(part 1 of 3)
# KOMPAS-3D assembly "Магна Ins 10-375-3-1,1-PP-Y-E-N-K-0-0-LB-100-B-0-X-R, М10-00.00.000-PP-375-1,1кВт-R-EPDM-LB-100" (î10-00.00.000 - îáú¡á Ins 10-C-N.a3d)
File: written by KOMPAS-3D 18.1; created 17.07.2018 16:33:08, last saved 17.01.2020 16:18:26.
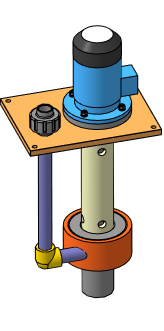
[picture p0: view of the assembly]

Document properties: Автор: Милов; Полное имя файла: C:\Users\User\Desktop\Магна 10 для Караби\М10-00.00.000 - Магна Ins 10-C-N.a3d

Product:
- Part/product: Магна Ins 10-375-3-1,1-PP-Y-E-N-K-0-0-LB-100-B-0-X-R  | designation М10-00.00.000-PP-375-1,1кВт-R-EPDM-LB-100
    Материал: Полипропилен  ГОСТ 26996-86 (density 900 kg/m3)
    Масса: 14.8749
  - Component [detail]: Всасывающая трубка 75  | designation L=100  | pos. 1375
      Материал: Полипропилен  ГОСТ 26996-86 (density 900 kg/m3)
      Масса: 0.190378
      Раздел спецификации: Детали
      Форматы листов документа: 3xA3
      Примечание: @100~)3xA3
      source file: D:\Magna\Магна Ins\Магна ins 11\Магна N\3Д\Магна INS 11\Всасывающая трубка 75.m3d, D:\Magna\Магна Ins\Магна ins 11\Магна N\3Д\Магна INS 11\Чертежи\М11-00.00.004-01 - Крышка.cdw
  - Component [detail]: Заглушка @2~25 FV PPR ф. "FV-Plast"  | qty 4  | pos. 12  | Материал: Полипропилен  ГОСТ 26996-86 (density 900 kg/m3); Масса: 0.0161976; Раздел спецификации: Прочие изделия
  - Component [standard]: Болт М10x1,25-6gx60 (S16) ГОСТ 7798-70  | qty 4  | pos. 8  | Масса: 0.0467; Раздел спецификации: Стандартные изделия; Рассекать на разрезах: no; additional columns: Сталь 12Х18Н10Т ГОСТ 5632-72
  - Component [standard]: Гайка М10x1,25-6H(S16) ГОСТ 5915-70  | qty 4  | pos. 9  | Масса: 0.01022; Раздел спецификации: Стандартные изделия; additional columns: М8-6H.21.12Х18Н10Т; Сталь 12Х18Н10Т ГОСТ 5632-72
  - Component [standard]: Шайба 10 ГОСТ 6402-70  | qty 4  | pos. 10  | Масса: 0.00201; Раздел спецификации: Стандартные изделия; Примечание: Нерж.; additional columns: 8; Без указания материала
  - Component [standard]: Шайба C.10.21 ГОСТ 11371-78  | qty 4  | pos. 11  | Материал: Сталь 12Х18Н10Т ГОСТ 5632-72 (density 1000 kg/m3); Масса: 0.003438; Раздел спецификации: Стандартные изделия; Рассекать на разрезах: no; additional columns: Сталь 12Х18Н10Т ГОСТ 5632-72
  - Component [standard]: Шайба C.10.21 ГОСТ 11371-78  | qty 4  | pos. 11  | Материал: Сталь 12Х18Н10Т ГОСТ 5632-72 (density 1000 kg/m3); Масса: 0.003438; Раздел спецификации: Стандартные изделия; additional columns: C.8.21; Сталь 12Х18Н10Т ГОСТ 5632-72
  - Component [detail]: Втулка ответная  | designation М10А-00.00.003-01  | pos. 6  | Масса: 0.031838; Раздел спецификации: Детали; Форматы листов документа: A4; Примечание: Заим.; source file: D:\AquaProf\АкваProf 190\3Д модель\..\..\..\Magna\Магна Ins\Магна ins 10\М10-00.00.000\3Д\М10А-00.00.003-01 - Втулка ответная.cdw, D:\AquaProf\АкваProf 190\3Д модель\М10А-00.00.003 - Втулка ответная.m3d
  - Component [detail]: Защитная втулка  | designation М10-00.00.003  | pos. 5  | Масса: 0.0193569; Раздел спецификации: Детали; Форматы листов документа: A4; source file: D:\Magna\Магна Ins\Магна ins 10\М10-00.00.000\3Д\М10-00.00.003 - Защитная втулка.cdw, М10-00.00.003 - Защитная втулка.m3d
  - Component [detail]: Импеллер Магна10  | designation М10-00.00.001  | pos. 3  | Масса: 0.169927; Раздел спецификации: Детали; Форматы листов документа: A3; source file: М10-00.00.001 - Импеллер Магна10.cdw, М10-00.00.001 - Импеллер Магна10.m3d
  - Component [detail]: Крышка  | designation М10-00.00.002-01  | pos. 4
      Материал: Полипропилен  ГОСТ 26996-86 (density 900 kg/m3)
      Масса: 0.284697
      Раздел спецификации: Детали
      Форматы листов документа: 4xA4
      Примечание: @100~)4xA4
      source file: М10-00.00.002 - Крышка.cdw, М10-00.00.002 - Крышка.m3d
  - Component [detail]: Электродвигатель / АИР 71B2 IM 3081 IP55 ф."Элком"  | pos. 14  | Масса: 8.3; Раздел спецификации: Прочие изделия; Примечание: См. заказ
  - Component [assembly]: Корпус полипропилен 375 1,1кВт  / с резьбовым переходником  | designation М10-00.20.000-PP-375-1,1кВт-R  | pos. 2  | Материал: Полипропилен  ГОСТ 26996-86 (density 900 kg/m3); Масса: 4.74348; Раздел спецификации: Сборочные единицы; Форматы листов документа: 3xA3; Примечание: @100~)3xA3@101~)3xA3
  - Component [standard]: Кольцо 125-130-25-1-0 ГОСТ 9833-73  | pos. 16  | Материал: Смесь резиновая ИРП-1068 ТУ 38-1051082-86 (density 1280 kg/m3); Масса: 0.00019; Раздел спецификации: Стандартные изделия; Рассекать на разрезах: no; additional columns: 125-130-25-1-0
  - Component [standard]: Кольцо 058-064-36-1-0 ГОСТ 9833-73  | pos. 15  | Материал: Смесь резиновая ИРП-1068 ТУ 38-1051082-86 (density 1280 kg/m3); Масса: 0.00194; Раздел спецификации: Стандартные изделия; Рассекать на разрезах: no; additional columns: 058-064-36-1-0
- Part/product: Магна Ins 10-375-3-0,55-PP-Y-V-N-K-0-0-L-0-B-0-X-R  | designation М10-00.00.000-PP-375-0,55кВт-R-Viton
    Материал: Полипропилен  ГОСТ 26996-86 (density 900 kg/m3)
    Масса: 11.3082
  - Component [detail]: Втулка ответная  | designation М10А-00.00.003-01  | pos. 6  | Масса: 0.031838; Раздел спецификации: Детали; Форматы листов документа: A4; Примечание: Заим.; source file: D:\AquaProf\АкваProf 190\3Д модель\..\..\..\Magna\Магна Ins\Магна ins 10\М10-00.00.000\3Д\М10А-00.00.003-01 - Втулка ответная.cdw, D:\AquaProf\АкваProf 190\3Д модель\М10А-00.00.003 - Втулка ответная.m3d
  - Component [detail]: Защитная втулка  | designation М10-00.00.003  | pos. 5  | Масса: 0.0193569; Раздел спецификации: Детали; Форматы листов документа: A4; source file: D:\Magna\Магна Ins\Магна ins 10\М10-00.00.000\3Д\М10-00.00.003 - Защитная втулка.cdw, М10-00.00.003 - Защитная втулка.m3d
  - Component [detail]: Импеллер Магна10  | designation М10-00.00.001  | pos. 3  | Масса: 0.169927; Раздел спецификации: Детали; Форматы листов документа: A3; source file: М10-00.00.001 - Импеллер Магна10.cdw, М10-00.00.001 - Импеллер Магна10.m3d
  - Component [detail]: Крышка  | designation М10-00.00.002  | pos. 4
      Материал: Полипропилен  ГОСТ 26996-86 (density 900 kg/m3)
      Масса: 0.324102
      Раздел спецификации: Детали
      Форматы листов документа: 4xA4
      Примечание: @100~)4xA4
      source file: М10-00.00.002 - Крышка.cdw, М10-00.00.002 - Крышка.m3d
  - Component [assembly]: Вал  | designation М10-00.15.000-0,55кВт-375  | pos. 1
      Материал: Полипропилен  ГОСТ 26996-86 (density 900 kg/m3)
      Масса: 0.519317
      Раздел спецификации: Сборочные единицы
      Форматы листов документа: 2xA3
      Примечание: @100~)2xA3
      source file: М10-00.15.000 - Вал.a3d
  - Component [assembly]: Корпус полипропилен 375 0,55 кВт  / с резьбовым переходником  | designation М10-00.20.000-PP-375-0,55кВт-R  | pos. 2
      Материал: Полипропилен  ГОСТ 26996-86 (density 900 kg/m3)
      Масса: 4.99986
      Раздел спецификации: Сборочные единицы
      Форматы листов документа: 3xA3
      Примечание: @100~)3xA3@101~)3xA3
      source file: М10-00.20.000 - Корпус.a3d
  - Component [detail]: Кольцо уплотнительное плоское 10-18-25  | designation Viton  | pos. 13  | Масса: 0.000562973; Раздел спецификации: Прочие изделия
- Part/product: Магна Ins 10-375-3-0,55-PP-Y-V-N-K-0-0-L-0-B-0-X-M  | designation М10-00.00.000-PP-375-0,55кВт-M-Viton
    Материал: Полипропилен  ГОСТ 26996-86 (density 900 kg/m3)
    Масса: 12.2247
  - Component [detail]: Втулка ответная  | designation М10А-00.00.003-01  | pos. 6  | Масса: 0.031838; Раздел спецификации: Детали; Форматы листов документа: A4; Примечание: Заим.; source file: D:\AquaProf\АкваProf 190\3Д модель\..\..\..\Magna\Магна Ins\Магна ins 10\М10-00.00.000\3Д\М10А-00.00.003-01 - Втулка ответная.cdw, D:\AquaProf\АкваProf 190\3Д модель\М10А-00.00.003 - Втулка ответная.m3d
  - Component [detail]: Защитная втулка  | designation М10-00.00.003  | pos. 5  | Масса: 0.0193569; Раздел спецификации: Детали; Форматы листов документа: A4; source file: D:\Magna\Магна Ins\Магна ins 10\М10-00.00.000\3Д\М10-00.00.003 - Защитная втулка.cdw, М10-00.00.003 - Защитная втулка.m3d
  - Component [detail]: Импеллер Магна10  | designation М10-00.00.001  | pos. 3  | Масса: 0.169927; Раздел спецификации: Детали; Форматы листов документа: A3; source file: М10-00.00.001 - Импеллер Магна10.cdw, М10-00.00.001 - Импеллер Магна10.m3d
  - Component [detail]: Крышка  | designation М10-00.00.002  | pos. 4
      Материал: Полипропилен  ГОСТ 26996-86 (density 900 kg/m3)
      Масса: 0.324102
      Раздел спецификации: Детали
      Форматы листов документа: 4xA4
      Примечание: @100~)4xA4
      source file: М10-00.00.002 - Крышка.cdw, М10-00.00.002 - Крышка.m3d
  - Component [assembly]: Вал  | designation М10-00.15.000-0,55кВт-375  | pos. 1
      Материал: Полипропилен  ГОСТ 26996-86 (density 900 kg/m3)
      Масса: 0.519317
      Раздел спецификации: Сборочные единицы
      Форматы листов документа: 2xA3
      Примечание: @100~)2xA3
      source file: М10-00.15.000 - Вал.a3d
  - Component [assembly]: Корпус полипропилен 375 0,55 кВт  / с разъёмной муфтой  | designation М10-00.20.000-PP-375-0,55кВт-M  | pos. 2
      Материал: Полипропилен  ГОСТ 26996-86 (density 900 kg/m3)
      Масса: 5.91637
      Раздел спецификации: Сборочные единицы
      Форматы листов документа: 3xA3
      Примечание: @100~)3xA3@101~)3xA3
      source file: М10-00.20.000 - Корпус.a3d
  - Component [detail]: Кольцо уплотнительное плоское 10-18-25  | designation Viton  | pos. 13  | Масса: 0.000562973; Раздел спецификации: Прочие изделия
- Part/product: Магна Ins 10-475-3-1,1-PP-Y-E-N-K-0-0-L-0-B-0-X-R  | designation М10-00.00.000-PP-475-1,1кВт-R
    Материал: Полипропилен  ГОСТ 26996-86 (density 900 kg/m3)
    Масса: 15.4162
  - Component [assembly]: Корпус полипропилен 475 1,1кВт  / с резьбовым переходником  | designation М10-00.20.000-PP-475-1,1кВт-R  | pos. 2  | Материал: Полипропилен  ГОСТ 26996-86 (density 900 kg/m3); Масса: 5.23433; Раздел спецификации: Сборочные единицы; Форматы листов документа: 3xA3; Примечание: @100~)3xA3@101~)3xA3
  - Component [detail]: Электродвигатель / АИР 71B2 IM 3081 IP55 ф."Элком"  | pos. 14  | Масса: 8.3; Раздел спецификации: Прочие изделия; Примечание: См. заказ
  - Component [assembly]: Вал  | designation М10-00.15.000-1,1кВт-475  | pos. 1
      Материал: Полипропилен  ГОСТ 26996-86 (density 900 kg/m3)
      Масса: 1.00808
      Раздел спецификации: Сборочные единицы
      Форматы листов документа: 2xA3
      Примечание: @100~)2xA3
      source file: М10-00.15.000 - Вал.a3d
  - Component [detail]: Крышка  | designation М10-00.00.002  | pos. 4
      Материал: Полипропилен  ГОСТ 26996-86 (density 900 kg/m3)
      Масса: 0.324102
      Раздел спецификации: Детали
      Форматы листов документа: 4xA4
      Примечание: @100~)4xA4
      source file: М10-00.00.002 - Крышка.cdw, М10-00.00.002 - Крышка.m3d
  - Component [detail]: Импеллер Магна10  | designation М10-00.00.001  | pos. 3  | Масса: 0.169927; Раздел спецификации: Детали; Форматы листов документа: A3; source file: М10-00.00.001 - Импеллер Магна10.cdw, М10-00.00.001 - Импеллер Магна10.m3d
  - Component [detail]: Защитная втулка  | designation М10-00.00.003  | pos. 5  | Масса: 0.0193569; Раздел спецификации: Детали; Форматы листов документа: A4; source file: D:\Magna\Магна Ins\Магна ins 10\М10-00.00.000\3Д\М10-00.00.003 - Защитная втулка.cdw, М10-00.00.003 - Защитная втулка.m3d
  - Component [detail]: Втулка ответная  | designation М10А-00.00.003-01  | pos. 6  | Масса: 0.031838; Раздел спецификации: Детали; Форматы листов документа: A4; Примечание: Заим.; source file: D:\AquaProf\АкваProf 190\3Д модель\..\..\..\Magna\Магна Ins\Магна ins 10\М10-00.00.000\3Д\М10А-00.00.003-01 - Втулка ответная.cdw, D:\AquaProf\АкваProf 190\3Д модель\М10А-00.00.003 - Втулка ответная.m3d
  - Component [standard]: Шайба C.10.21 ГОСТ 11371-78  | qty 4  | pos. 11  | Материал: Сталь 12Х18Н10Т ГОСТ 5632-72 (density 1000 kg/m3); Масса: 0.003438; Раздел спецификации: Стандартные изделия; additional columns: C.8.21; Сталь 12Х18Н10Т ГОСТ 5632-72
  - Component [standard]: Шайба C.10.21 ГОСТ 11371-78  | qty 4  | pos. 11  | Материал: Сталь 12Х18Н10Т ГОСТ 5632-72 (density 1000 kg/m3); Масса: 0.003438; Раздел спецификации: Стандартные изделия; Рассекать на разрезах: no; additional columns: Сталь 12Х18Н10Т ГОСТ 5632-72
  - Component [standard]: Шайба 10 ГОСТ 6402-70  | qty 4  | pos. 10  | Масса: 0.00201; Раздел спецификации: Стандартные изделия; Примечание: Нерж.; Рассекать на разрезах: no; additional columns: 10; Без указания материала
  - Component [standard]: Гайка М10x1,25-6H(S16) ГОСТ 5915-70  | qty 4  | pos. 9  | Масса: 0.01022; Раздел спецификации: Стандартные изделия; Рассекать на разрезах: no; additional columns: М10x1,25-6H (S16); Сталь 12Х18Н10Т ГОСТ 5632-72
  - Component [standard]: Болт М10-6gx60.21.12Х18Н10Т ГОСТ 7798-70  | qty 4  | pos. 8  | Масса: 0.0467; Раздел спецификации: Стандартные изделия; additional columns: М8-6gx55.21.12Х18Н10Т; Сталь 12Х18Н10Т ГОСТ 5632-72
  - Component [detail]: Заглушка @2~25 FV PPR ф. "FV-Plast"  | qty 4  | pos. 12  | Материал: Полипропилен  ГОСТ 26996-86 (density 900 kg/m3); Масса: 0.0161976; Раздел спецификации: Прочие изделия
- Part/product: Магна Ins 10-475-3-1,1-PP-Y-E-N-K-0-0-L-0-B-0-X-M  | designation М10-00.00.000-PP-475-1,1кВт-M
    Материал: Полипропилен  ГОСТ 26996-86 (density 900 kg/m3)
    Масса: 16.3327
  - Component [assembly]: Корпус полипропилен 475 1,1кВт с разъёмной муфтой  | designation М10-00.20.000-PP-475-1,1кВт-M  | pos. 2  | Материал: Полипропилен  ГОСТ 26996-86 (density 900 kg/m3); Масса: 6.15084; Раздел спецификации: Сборочные единицы; Форматы листов документа: 3xA3; Примечание: @100~)3xA3@101~)3xA3
  - Component [detail]: Электродвигатель / АИР 71B2 IM 3081 IP55 ф."Элком"  | pos. 14  | Масса: 8.3; Раздел спецификации: Прочие изделия; Примечание: См. заказ
  - Component [assembly]: Вал  | designation М10-00.15.000-1,1кВт-475  | pos. 1
      Материал: Полипропилен  ГОСТ 26996-86 (density 900 kg/m3)
      Масса: 1.00808
      Раздел спецификации: Сборочные единицы
      Форматы листов документа: 2xA3
      Примечание: @100~)2xA3
      source file: М10-00.15.000 - Вал.a3d
  - Component [detail]: Крышка  | designation М10-00.00.002  | pos. 4
      Материал: Полипропилен  ГОСТ 26996-86 (density 900 kg/m3)
      Масса: 0.324102
      Раздел спецификации: Детали
      Форматы листов документа: 4xA4
      Примечание: @100~)4xA4
      source file: М10-00.00.002 - Крышка.cdw, М10-00.00.002 - Крышка.m3d
  - Component [detail]: Импеллер Магна10  | designation М10-00.00.001  | pos. 3  | Масса: 0.169927; Раздел спецификации: Детали; Форматы листов документа: A3; source file: М10-00.00.001 - Импеллер Магна10.cdw, М10-00.00.001 - Импеллер Магна10.m3d
  - Component [detail]: Защитная втулка  | designation М10-00.00.003  | pos. 5  | Масса: 0.0193569; Раздел спецификации: Детали; Форматы листов документа: A4; source file: D:\Magna\Магна Ins\Магна ins 10\М10-00.00.000\3Д\М10-00.00.003 - Защитная втулка.cdw, М10-00.00.003 - Защитная втулка.m3d
  - Component [detail]: Втулка ответная  | designation М10А-00.00.003-01  | pos. 6  | Масса: 0.031838; Раздел спецификации: Детали; Форматы листов документа: A4; Примечание: Заим.; source file: D:\AquaProf\АкваProf 190\3Д модель\..\..\..\Magna\Магна Ins\Магна ins 10\М10-00.00.000\3Д\М10А-00.00.003-01 - Втулка ответная.cdw, D:\AquaProf\АкваProf 190\3Д модель\М10А-00.00.003 - Втулка ответная.m3d
  - Component [standard]: Шайба C.10.21 ГОСТ 11371-78  | qty 4  | pos. 11  | Материал: Сталь 12Х18Н10Т ГОСТ 5632-72 (density 1000 kg/m3); Масса: 0.003438; Раздел спецификации: Стандартные изделия; additional columns: C.8.21; Сталь 12Х18Н10Т ГОСТ 5632-72
  - Component [standard]: Шайба C.10.21 ГОСТ 11371-78  | qty 4  | pos. 11  | Материал: Сталь 12Х18Н10Т ГОСТ 5632-72 (density 1000 kg/m3); Масса: 0.003438; Раздел спецификации: Стандартные изделия; Рассекать на разрезах: no; additional columns: Сталь 12Х18Н10Т ГОСТ 5632-72
  - Component [standard]: Шайба 10 ГОСТ 6402-70  | qty 4  | pos. 10  | Масса: 0.00201; Раздел спецификации: Стандартные изделия; Примечание: Нерж.; Рассекать на разрезах: no; additional columns: 10; Без указания материала
  - Component [standard]: Гайка М10x1,25-6H(S16) ГОСТ 5915-70  | qty 4  | pos. 9  | Масса: 0.01022; Раздел спецификации: Стандартные изделия; Рассекать на разрезах: no; additional columns: М10x1,25-6H (S16); Сталь 12Х18Н10Т ГОСТ 5632-72
  - Component [standard]: Болт М10-6gx60.21.12Х18Н10Т ГОСТ 7798-70  | qty 4  | pos. 8  | Масса: 0.0467; Раздел спецификации: Стандартные изделия; additional columns: М8-6gx55.21.12Х18Н10Т; Сталь 12Х18Н10Т ГОСТ 5632-72
  - Component [detail]: Заглушка @2~25 FV PPR ф. "FV-Plast"  | qty 4  | pos. 12  | Материал: Полипропилен  ГОСТ 26996-86 (density 900 kg/m3); Масса: 0.0161976; Раздел спецификации: Прочие изделия
- Part/product: Магна Ins 10-475-3-0,55-PP-Y-E-N-K-0-0-L-0-B-0-X-R  | designation М10-00.00.000-PP-475-0,75кВт-R
    Материал: Полипропилен  ГОСТ 26996-86 (density 900 kg/m3)
    Масса: 15.4187
  - Component [assembly]: Корпус полипропилен 475 0,75кВт м резьбовым переходником  | designation М10-00.20.000-PP-475-0,75кВт-R  | pos. 2  | Материал: Полипропилен  ГОСТ 26996-86 (density 900 kg/m3); Масса: 5.23433; Раздел спецификации: Сборочные единицы; Форматы листов документа: 3xA3; Примечание: @100~)3xA3@101~)3xA3
  - Component [assembly]: Вал  | designation М10-00.15.000-0,75кВт-475  | pos. 1
      Материал: Полипропилен  ГОСТ 26996-86 (density 900 kg/m3)
      Масса: 1.01058
      Раздел спецификации: Сборочные единицы
      Форматы листов документа: 2xA3
      Примечание: @100~)2xA3
      source file: М10-00.15.000 - Вал.a3d
  - Component [detail]: Крышка  | designation М10-00.00.002  | pos. 4
      Материал: Полипропилен  ГОСТ 26996-86 (density 900 kg/m3)
      Масса: 0.324102
      Раздел спецификации: Детали
      Форматы листов документа: 4xA4
      Примечание: @100~)4xA4
      source file: М10-00.00.002 - Крышка.cdw, М10-00.00.002 - Крышка.m3d
  - Component [detail]: Импеллер Магна10  | designation М10-00.00.001  | pos. 3  | Масса: 0.169927; Раздел спецификации: Детали; Форматы листов документа: A3; source file: М10-00.00.001 - Импеллер Магна10.cdw, М10-00.00.001 - Импеллер Магна10.m3d
  - Component [detail]: Защитная втулка  | designation М10-00.00.003  | pos. 5  | Масса: 0.0193569; Раздел спецификации: Детали; Форматы листов документа: A4; source file: D:\Magna\Магна Ins\Магна ins 10\М10-00.00.000\3Д\М10-00.00.003 - Защитная втулка.cdw, М10-00.00.003 - Защитная втулка.m3d
  - Component [detail]: Втулка ответная  | designation М10А-00.00.003-01  | pos. 6  | Масса: 0.031838; Раздел спецификации: Детали; Форматы листов документа: A4; Примечание: Заим.; source file: D:\AquaProf\АкваProf 190\3Д модель\..\..\..\Magna\Магна Ins\Магна ins 10\М10-00.00.000\3Д\М10А-00.00.003-01 - Втулка ответная.cdw, D:\AquaProf\АкваProf 190\3Д модель\М10А-00.00.003 - Втулка ответная.m3d
  - Component [standard]: Шайба C.10.21 ГОСТ 11371-78  | qty 4  | pos. 11  | Материал: Сталь 12Х18Н10Т ГОСТ 5632-72 (density 1000 kg/m3); Масса: 0.003438; Раздел спецификации: Стандартные изделия; additional columns: C.8.21; Сталь 12Х18Н10Т ГОСТ 5632-72
  - Component [standard]: Шайба C.10.21 ГОСТ 11371-78  | qty 4  | pos. 11  | Материал: Сталь 12Х18Н10Т ГОСТ 5632-72 (density 1000 kg/m3); Масса: 0.003438; Раздел спецификации: Стандартные изделия; Рассекать на разрезах: no; additional columns: Сталь 12Х18Н10Т ГОСТ 5632-72
  - Component [standard]: Шайба 10 ГОСТ 6402-70  | qty 4  | pos. 10  | Масса: 0.00201; Раздел спецификации: Стандартные изделия; Примечание: Нерж.; Рассекать на разрезах: no; additional columns: 10; Без указания материала
  - Component [standard]: Гайка М10x1,25-6H(S16) ГОСТ 5915-70  | qty 4  | pos. 9  | Масса: 0.01022; Раздел спецификации: Стандартные изделия; Рассекать на разрезах: no; additional columns: М10x1,25-6H (S16); Сталь 12Х18Н10Т ГОСТ 5632-72
  - Component [standard]: Болт М8-6gx60.21.12Х18Н10Т ГОСТ 7798-70  | qty 4  | pos. 8  | Масса: 0.0467; Раздел спецификации: Стандартные изделия; additional columns: М8-6gx55.21.12Х18Н10Т; Сталь 12Х18Н10Т ГОСТ 5632-72
  - Component [detail]: Заглушка @2~25 FV PPR ф. "FV-Plast"  | qty 4  | pos. 12  | Материал: Полипропилен  ГОСТ 26996-86 (density 900 kg/m3); Масса: 0.0161976; Раздел спецификации: Прочие изделия
- Part/product: Магна Ins 10-475-3-0,75-PP-Y-E-N-K-0-0-L-0-B-0-X-M  | designation М10-00.00.000-PP-475-0,75кВт-M
    Материал: Полипропилен  ГОСТ 26996-86 (density 900 kg/m3)
    Масса: 16.3352
  - Component [assembly]: Корпус полипропилен 475 0,75кВт  / с разъёмной муфтой  | designation М10-00.20.000-PP-475-0,75кВт-M  | pos. 2  | Материал: Полипропилен  ГОСТ 26996-86 (density 900 kg/m3); Масса: 6.15084; Раздел спецификации: Сборочные единицы; Форматы листов документа: 3xA3; Примечание: @100~)3xA3@101~)3xA3
  - Component [assembly]: Вал  | designation М10-00.15.000-0,75кВт-475  | pos. 1
      Материал: Полипропилен  ГОСТ 26996-86 (density 900 kg/m3)
      Масса: 1.01058
      Раздел спецификации: Сборочные единицы
      Форматы листов документа: 2xA3
      Примечание: @100~)2xA3
      source file: М10-00.15.000 - Вал.a3d
  - Component [detail]: Крышка  | designation М10-00.00.002  | pos. 4
      Материал: Полипропилен  ГОСТ 26996-86 (density 900 kg/m3)
      Масса: 0.324102
      Раздел спецификации: Детали
      Форматы листов документа: 4xA4
      Примечание: @100~)4xA4
      source file: М10-00.00.002 - Крышка.cdw, М10-00.00.002 - Крышка.m3d
  - Component [detail]: Импеллер Магна10  | designation М10-00.00.001  | pos. 3  | Масса: 0.169927; Раздел спецификации: Детали; Форматы листов документа: A3; source file: М10-00.00.001 - Импеллер Магна10.cdw, М10-00.00.001 - Импеллер Магна10.m3d
  - Component [detail]: Защитная втулка  | designation М10-00.00.003  | pos. 5  | Масса: 0.0193569; Раздел спецификации: Детали; Форматы листов документа: A4; source file: D:\Magna\Магна Ins\Магна ins 10\М10-00.00.000\3Д\М10-00.00.003 - Защитная втулка.cdw, М10-00.00.003 - Защитная втулка.m3d
  - Component [detail]: Втулка ответная  | designation М10А-00.00.003-01  | pos. 6  | Масса: 0.031838; Раздел спецификации: Детали; Форматы листов документа: A4; Примечание: Заим.; source file: D:\AquaProf\АкваProf 190\3Д модель\..\..\..\Magna\Магна Ins\Магна ins 10\М10-00.00.000\3Д\М10А-00.00.003-01 - Втулка ответная.cdw, D:\AquaProf\АкваProf 190\3Д модель\М10А-00.00.003 - Втулка ответная.m3d
  - Component [standard]: Шайба C.10.21 ГОСТ 11371-78  | qty 4  | pos. 11  | Материал: Сталь 12Х18Н10Т ГОСТ 5632-72 (density 1000 kg/m3); Масса: 0.003438; Раздел спецификации: Стандартные изделия; additional columns: C.8.21; Сталь 12Х18Н10Т ГОСТ 5632-72
  - Component [standard]: Шайба C.10.21 ГОСТ 11371-78  | qty 4  | pos. 11  | Материал: Сталь 12Х18Н10Т ГОСТ 5632-72 (density 1000 kg/m3); Масса: 0.003438; Раздел спецификации: Стандартные изделия; Рассекать на разрезах: no; additional columns: Сталь 12Х18Н10Т ГОСТ 5632-72
  - Component [standard]: Шайба 10 ГОСТ 6402-70  | qty 4  | pos. 10  | Масса: 0.00201; Раздел спецификации: Стандартные изделия; Примечание: Нерж.; Рассекать на разрезах: no; additional columns: 10; Без указания материала
  - Component [standard]: Гайка М10x1,25-6H(S16) ГОСТ 5915-70  | qty 4  | pos. 9  | Масса: 0.01022; Раздел спецификации: Стандартные изделия; Рассекать на разрезах: no; additional columns: М10x1,25-6H (S16); Сталь 12Х18Н10Т ГОСТ 5632-72
  - Component [standard]: Болт М8-6gx60.21.12Х18Н10Т ГОСТ 7798-70  | qty 4  | pos. 8  | Масса: 0.0467; Раздел спецификации: Стандартные изделия; additional columns: М8-6gx55.21.12Х18Н10Т; Сталь 12Х18Н10Т ГОСТ 5632-72
  - Component [detail]: Заглушка @2~25 FV PPR ф. "FV-Plast"  | qty 4  | pos. 12  | Материал: Полипропилен  ГОСТ 26996-86 (density 900 kg/m3); Масса: 0.0161976; Раздел спецификации: Прочие изделия
- Part/product: Магна Ins 10-475-3-0,55-PP-Y-E-N-K-0-0-L-0-B-0-X-R  | designation М10-00.00.000-PP-475-0,55кВт-R
    Материал: Полипропилен  ГОСТ 26996-86 (density 900 kg/m3)
    Масса: 11.9222
  - Component [assembly]: Корпус полипропилен 475 0,55кВт  / с резьбовым переходником  | designation М10-00.20.000-PP-475-0,55кВт-R  | pos. 2  | Материал: Полипропилен  ГОСТ 26996-86 (density 900 kg/m3); Масса: 5.49071; Раздел спецификации: Сборочные единицы; Форматы листов документа: 3xA3; Примечание: @100~)3xA3@101~)3xA3
  - Component [assembly]: Вал  | designation М10-00.15.000-0,55кВт-475  | pos. 1
      Материал: Полипропилен  ГОСТ 26996-86 (density 900 kg/m3)
      Масса: 0.642468
      Раздел спецификации: Сборочные единицы
      Форматы листов документа: 2xA3
      Примечание: @100~)2xA3
      source file: М10-00.15.000 - Вал.a3d
  - Component [detail]: Крышка  | designation М10-00.00.002  | pos. 4
      Материал: Полипропилен  ГОСТ 26996-86 (density 900 kg/m3)
      Масса: 0.324102
      Раздел спецификации: Детали
      Форматы листов документа: 4xA4
      Примечание: @100~)4xA4
      source file: М10-00.00.002 - Крышка.cdw, М10-00.00.002 - Крышка.m3d
  - Component [detail]: Импеллер Магна10  | designation М10-00.00.001  | pos. 3  | Масса: 0.169927; Раздел спецификации: Детали; Форматы листов документа: A3; source file: М10-00.00.001 - Импеллер Магна10.cdw, М10-00.00.001 - Импеллер Магна10.m3d
  - Component [detail]: Защитная втулка  | designation М10-00.00.003  | pos. 5  | Масса: 0.0193569; Раздел спецификации: Детали; Форматы листов документа: A4; source file: D:\Magna\Магна Ins\Магна ins 10\М10-00.00.000\3Д\М10-00.00.003 - Защитная втулка.cdw, М10-00.00.003 - Защитная втулка.m3d
  - Component [detail]: Втулка ответная  | designation М10А-00.00.003-01  | pos. 6  | Масса: 0.031838; Раздел спецификации: Детали; Форматы листов документа: A4; Примечание: Заим.; source file: D:\AquaProf\АкваProf 190\3Д модель\..\..\..\Magna\Магна Ins\Магна ins 10\М10-00.00.000\3Д\М10А-00.00.003-01 - Втулка ответная.cdw, D:\AquaProf\АкваProf 190\3Д модель\М10А-00.00.003 - Втулка ответная.m3d
- Part/product: Магна Ins 10-475-3-0,55-PP-Y-E-N-K-0-0-L-0-B-0-X-M  | designation М10-00.00.000-PP-475-0,55кВт-M
    Материал: Полипропилен  ГОСТ 26996-86 (density 900 kg/m3)
    Масса: 12.8387
  - Component [assembly]: Корпус полипропилен 475 0,55кВт  / с разъёмной муфтой  | designation М10-00.20.000-PP-475-0,55кВт-M  | pos. 2  | Материал: Полипропилен  ГОСТ 26996-86 (density 900 kg/m3); Масса: 6.40722; Раздел спецификации: Сборочные единицы; Форматы листов документа: 3xA3; Примечание: @100~)3xA3@101~)3xA3
  - Component [assembly]: Вал  | designation М10-00.15.000-0,55кВт-475  | pos. 1
      Материал: Полипропилен  ГОСТ 26996-86 (density 900 kg/m3)
      Масса: 0.642468
      Раздел спецификации: Сборочные единицы
      Форматы листов документа: 2xA3
      Примечание: @100~)2xA3
      source file: М10-00.15.000 - Вал.a3d
  - Component [detail]: Крышка  | designation М10-00.00.002  | pos. 4
      Материал: Полипропилен  ГОСТ 26996-86 (density 900 kg/m3)
      Масса: 0.324102
      Раздел спецификации: Детали
      Форматы листов документа: 4xA4
      Примечание: @100~)4xA4
      source file: М10-00.00.002 - Крышка.cdw, М10-00.00.002 - Крышка.m3d
  - Component [detail]: Импеллер Магна10  | designation М10-00.00.001  | pos. 3  | Масса: 0.169927; Раздел спецификации: Детали; Форматы листов документа: A3; source file: М10-00.00.001 - Импеллер Магна10.cdw, М10-00.00.001 - Импеллер Магна10.m3d
  - Component [detail]: Защитная втулка  | designation М10-00.00.003  | pos. 5  | Масса: 0.0193569; Раздел спецификации: Детали; Форматы листов документа: A4; source file: D:\Magna\Магна Ins\Магна ins 10\М10-00.00.000\3Д\М10-00.00.003 - Защитная втулка.cdw, М10-00.00.003 - Защитная втулка.m3d
  - Component [detail]: Втулка ответная  | designation М10А-00.00.003-01  | pos. 6  | Масса: 0.031838; Раздел спецификации: Детали; Форматы листов документа: A4; Примечание: Заим.; source file: D:\AquaProf\АкваProf 190\3Д модель\..\..\..\Magna\Магна Ins\Магна ins 10\М10-00.00.000\3Д\М10А-00.00.003-01 - Втулка ответная.cdw, D:\AquaProf\АкваProf 190\3Д модель\М10А-00.00.003 - Втулка ответная.m3d
- Part/product: Магна Ins 10-PP-475-1,1кВт  | designation М10-00.00.000-PP-475-1,1кВт
    Материал: Полипропилен  ГОСТ 26996-86 (density 900 kg/m3)
    Масса: 15.3833
  - Component [detail]: Заглушка @2~25 FV PPR ф. "FV-Plast"  | qty 4  | pos. 12  | Материал: Полипропилен  ГОСТ 26996-86 (density 900 kg/m3); Масса: 0.0161976; Раздел спецификации: Прочие изделия
  - Component [standard]: Болт М10x1,25-6gx60 (S16) ГОСТ 7798-70  | qty 4  | pos. 8  | Масса: 0.0467; Раздел спецификации: Стандартные изделия; Рассекать на разрезах: no; additional columns: Сталь 12Х18Н10Т ГОСТ 5632-72
  - Component [standard]: Гайка М10x1,25-6H(S16) ГОСТ 5915-70  | qty 4  | pos. 9  | Масса: 0.01022; Раздел спецификации: Стандартные изделия; Рассекать на разрезах: no; additional columns: М10x1,25-6H (S16); Сталь 12Х18Н10Т ГОСТ 5632-72
  - Component [standard]: Шайба 10 ГОСТ 6402-70  | qty 4  | pos. 10  | Масса: 0.00201; Раздел спецификации: Стандартные изделия; Примечание: Нерж.; Рассекать на разрезах: no; additional columns: 10; Без указания материала
  - Component [standard]: Шайба C.10.21 ГОСТ 11371-78  | qty 8  | pos. 11  | Материал: Сталь 12Х18Н10Т ГОСТ 5632-72 (density 1000 kg/m3); Масса: 0.003438; Раздел спецификации: Стандартные изделия; Рассекать на разрезах: no; additional columns: Сталь 12Х18Н10Т ГОСТ 5632-72
  - Component [detail]: Втулка ответная  | designation М10А-00.00.003-01  | pos. 6  | Масса: 0.031838; Раздел спецификации: Детали; Форматы листов документа: A4; Примечание: Заим.; source file: D:\AquaProf\АкваProf 190\3Д модель\..\..\..\Magna\Магна Ins\Магна ins 10\М10-00.00.000\3Д\М10А-00.00.003-01 - Втулка ответная.cdw, D:\AquaProf\АкваProf 190\3Д модель\М10А-00.00.003 - Втулка ответная.m3d
  - Component [detail]: Защитная втулка  | designation М10-00.00.003  | pos. 5  | Масса: 0.0193569; Раздел спецификации: Детали; Форматы листов документа: A4; source file: D:\Magna\Магна Ins\Магна ins 10\М10-00.00.000\3Д\М10-00.00.003 - Защитная втулка.cdw, М10-00.00.003 - Защитная втулка.m3d
  - Component [detail]: Импеллер Магна10  | designation М10-00.00.001  | pos. 3  | Масса: 0.169927; Раздел спецификации: Детали; Форматы листов документа: A3; source file: М10-00.00.001 - Импеллер Магна10.cdw, М10-00.00.001 - Импеллер Магна10.m3d
  - Component [detail]: Крышка  | designation М10-00.00.002  | pos. 4
      Материал: Полипропилен  ГОСТ 26996-86 (density 900 kg/m3)
      Масса: 0.324102
      Раздел спецификации: Детали
      Форматы листов документа: 4xA4
      Примечание: @100~)4xA4
      source file: М10-00.00.002 - Крышка.cdw, М10-00.00.002 - Крышка.m3d
  - Component [assembly]: Вал  | designation М10-00.15.000-1,1кВт-475  | pos. 1
      Материал: Полипропилен  ГОСТ 26996-86 (density 900 kg/m3)
      Масса: 1.00808
      Раздел спецификации: Сборочные единицы
      Форматы листов документа: 2xA3
      Примечание: @100~)2xA3
      source file: М10-00.15.000 - Вал.a3d
  - Component [detail]: Электродвигатель / АИР 71B2 IM 3081 IP55 ф."Элком"  | pos. 14  | Масса: 8.3; Раздел спецификации: Прочие изделия; Примечание: См. заказ
  - Component [assembly]: Корпус полипропилен 475 1,1кВт  | designation М10-00.20.000-PP-475-1,1кВт  | pos. 2  | Материал: Полипропилен  ГОСТ 26996-86 (density 900 kg/m3); Масса: 5.20146; Раздел спецификации: Сборочные единицы; Форматы листов документа: 3xA3; Примечание: @100~)3xA3@101~)3xA3
- Part/product: Магна Ins 10-PP-475-0,75кВт  | designation М10-00.00.000-PP-475-0,75кВт
    Материал: Полипропилен  ГОСТ 26996-86 (density 900 kg/m3)
    Масса: 15.3858
  - Component [detail]: Заглушка @2~25 FV PPR ф. "FV-Plast"  | qty 4  | pos. 12  | Материал: Полипропилен  ГОСТ 26996-86 (density 900 kg/m3); Масса: 0.0161976; Раздел спецификации: Прочие изделия
  - Component [standard]: Болт М10x1,25-6gx60 (S16) ГОСТ 7798-70  | qty 4  | pos. 8  | Масса: 0.0467; Раздел спецификации: Стандартные изделия; Рассекать на разрезах: no; additional columns: Сталь 12Х18Н10Т ГОСТ 5632-72
  - Component [standard]: Гайка М10x1,25-6H(S16) ГОСТ 5915-70  | qty 4  | pos. 9  | Масса: 0.01022; Раздел спецификации: Стандартные изделия; Рассекать на разрезах: no; additional columns: М10x1,25-6H (S16); Сталь 12Х18Н10Т ГОСТ 5632-72
  - Component [standard]: Шайба 10 ГОСТ 6402-70  | qty 4  | pos. 10  | Масса: 0.00201; Раздел спецификации: Стандартные изделия; Примечание: Нерж.; Рассекать на разрезах: no; additional columns: 10; Без указания материала
  - Component [standard]: Шайба C.10.21 ГОСТ 11371-78  | qty 8  | pos. 11  | Материал: Сталь 12Х18Н10Т ГОСТ 5632-72 (density 1000 kg/m3); Масса: 0.003438; Раздел спецификации: Стандартные изделия; Рассекать на разрезах: no; additional columns: Сталь 12Х18Н10Т ГОСТ 5632-72
  - Component [detail]: Втулка ответная  | designation М10А-00.00.003-01  | pos. 6  | Масса: 0.031838; Раздел спецификации: Детали; Форматы листов документа: A4; Примечание: Заим.; source file: D:\AquaProf\АкваProf 190\3Д модель\..\..\..\Magna\Магна Ins\Магна ins 10\М10-00.00.000\3Д\М10А-00.00.003-01 - Втулка ответная.cdw, D:\AquaProf\АкваProf 190\3Д модель\М10А-00.00.003 - Втулка ответная.m3d
  - Component [detail]: Защитная втулка  | designation М10-00.00.003  | pos. 5  | Масса: 0.0193569; Раздел спецификации: Детали; Форматы листов документа: A4; source file: D:\Magna\Магна Ins\Магна ins 10\М10-00.00.000\3Д\М10-00.00.003 - Защитная втулка.cdw, М10-00.00.003 - Защитная втулка.m3d
  - Component [detail]: Импеллер Магна10  | designation М10-00.00.001  | pos. 3  | Масса: 0.169927; Раздел спецификации: Детали; Форматы листов документа: A3; source file: М10-00.00.001 - Импеллер Магна10.cdw, М10-00.00.001 - Импеллер Магна10.m3d
  - Component [detail]: Крышка  | designation М10-00.00.002  | pos. 4
      Материал: Полипропилен  ГОСТ 26996-86 (density 900 kg/m3)
      Масса: 0.324102
      Раздел спецификации: Детали
      Форматы листов документа: 4xA4
      Примечание: @100~)4xA4
      source file: М10-00.00.002 - Крышка.cdw, М10-00.00.002 - Крышка.m3d
  - Component [assembly]: Вал  | designation М10-00.15.000-0,75кВт-475  | pos. 1
      Материал: Полипропилен  ГОСТ 26996-86 (density 900 kg/m3)
      Масса: 1.01058
      Раздел спецификации: Сборочные единицы
      Форматы листов документа: 2xA3
      Примечание: @100~)2xA3
      source file: М10-00.15.000 - Вал.a3d
  - Component [assembly]: Корпус полипропилен 475 0,75кВт  | designation М10-00.20.000-PP-475-0,75кВт  | pos. 2  | Материал: Полипропилен  ГОСТ 26996-86 (density 900 kg/m3); Масса: 5.20146; Раздел спецификации: Сборочные единицы; Форматы листов документа: 3xA3; Примечание: @100~)3xA3@101~)3xA3
- Part/product: Магна Ins 10-PP-475-0,55кВт  | designation М10-00.00.000-PP-475-0,55кВт
    Материал: Полипропилен  ГОСТ 26996-86 (density 900 kg/m3)
    Масса: 11.8893
  - Component [detail]: Втулка ответная  | designation М10А-00.00.003-01  | pos. 6  | Масса: 0.031838; Раздел спецификации: Детали; Форматы листов документа: A4; Примечание: Заим.; source file: D:\AquaProf\АкваProf 190\3Д модель\..\..\..\Magna\Магна Ins\Магна ins 10\М10-00.00.000\3Д\М10А-00.00.003-01 - Втулка ответная.cdw, D:\AquaProf\АкваProf 190\3Д модель\М10А-00.00.003 - Втулка ответная.m3d
  - Component [detail]: Защитная втулка  | designation М10-00.00.003  | pos. 5  | Масса: 0.0193569; Раздел спецификации: Детали; Форматы листов документа: A4; source file: D:\Magna\Магна Ins\Магна ins 10\М10-00.00.000\3Д\М10-00.00.003 - Защитная втулка.cdw, М10-00.00.003 - Защитная втулка.m3d
  - Component [detail]: Импеллер Магна10  | designation М10-00.00.001  | pos. 3  | Масса: 0.169927; Раздел спецификации: Детали; Форматы листов документа: A3; source file: М10-00.00.001 - Импеллер Магна10.cdw, М10-00.00.001 - Импеллер Магна10.m3d
  - Component [detail]: Крышка  | designation М10-00.00.002  | pos. 4
      Материал: Полипропилен  ГОСТ 26996-86 (density 900 kg/m3)
      Масса: 0.324102
      Раздел спецификации: Детали
      Форматы листов документа: 4xA4
      Примечание: @100~)4xA4
      source file: М10-00.00.002 - Крышка.cdw, М10-00.00.002 - Крышка.m3d
  - Component [assembly]: Вал  | designation М10-00.15.000-0,55кВт-475  | pos. 1
      Материал: Полипропилен  ГОСТ 26996-86 (density 900 kg/m3)
      Масса: 0.642468
      Раздел спецификации: Сборочные единицы
      Форматы листов документа: 2xA3
      Примечание: @100~)2xA3
      source file: М10-00.15.000 - Вал.a3d
  - Component [assembly]: Корпус полипропилен  | designation М10-00.20.000-PP-475  | pos. 2  | Материал: Полипропилен  ГОСТ 26996-86 (density 900 kg/m3); Масса: 5.45783; Раздел спецификации: Сборочные единицы; Форматы листов документа: 3xA3; Примечание: @100~)3xA3@101~)3xA3
- Part/product: Магна Ins 10-375-3-1,1-PP-Y-E-N-K-0-0-L-0-B-0-X-R  | designation М10-00.00.000-PP-375-1,1кВт-R-EPDM
    Материал: Полипропилен  ГОСТ 26996-86 (density 900 kg/m3)
    Масса: 14.7218
  - Component [assembly]: Корпус полипропилен 375 1,1кВт  / с резьбовым переходником  | designation М10-00.20.000-PP-375-1,1кВт-R  | pos. 2  | Материал: Полипропилен  ГОСТ 26996-86 (density 900 kg/m3); Масса: 4.74348; Раздел спецификации: Сборочные единицы; Форматы листов документа: 3xA3; Примечание: @100~)3xA3@101~)3xA3
  - Component [detail]: Электродвигатель / АИР 71B2 IM 3081 IP55 ф."Элком"  | pos. 14  | Масса: 8.3; Раздел спецификации: Прочие изделия; Примечание: См. заказ
  - Component [assembly]: Вал  | designation М10-00.15.000-1,1кВт-375  | pos. 1
      Материал: Полипропилен  ГОСТ 26996-86 (density 900 kg/m3)
      Масса: 0.804509
      Раздел спецификации: Сборочные единицы
      Форматы листов документа: 2xA3
      Примечание: @100~)2xA3
      source file: М10-00.15.000 - Вал.a3d
  - Component [detail]: Крышка  | designation М10-00.00.002  | pos. 4
      Материал: Полипропилен  ГОСТ 26996-86 (density 900 kg/m3)
      Масса: 0.324102
      Раздел спецификации: Детали
      Форматы листов документа: 4xA4
      Примечание: @100~)4xA4
      source file: М10-00.00.002 - Крышка.cdw, М10-00.00.002 - Крышка.m3d
  - Component [detail]: Импеллер Магна10  | designation М10-00.00.001  | pos. 3  | Масса: 0.169927; Раздел спецификации: Детали; Форматы листов документа: A3; source file: М10-00.00.001 - Импеллер Магна10.cdw, М10-00.00.001 - Импеллер Магна10.m3d
  - Component [detail]: Защитная втулка  | designation М10-00.00.003  | pos. 5  | Масса: 0.0193569; Раздел спецификации: Детали; Форматы листов документа: A4; source file: D:\Magna\Магна Ins\Магна ins 10\М10-00.00.000\3Д\М10-00.00.003 - Защитная втулка.cdw, М10-00.00.003 - Защитная втулка.m3d
  - Component [detail]: Втулка ответная  | designation М10А-00.00.003-01  | pos. 6  | Масса: 0.031838; Раздел спецификации: Детали; Форматы листов документа: A4; Примечание: Заим.; source file: D:\AquaProf\АкваProf 190\3Д модель\..\..\..\Magna\Магна Ins\Магна ins 10\М10-00.00.000\3Д\М10А-00.00.003-01 - Втулка ответная.cdw, D:\AquaProf\АкваProf 190\3Д модель\М10А-00.00.003 - Втулка ответная.m3d
  - Component [standard]: Шайба C.10.21 ГОСТ 11371-78  | qty 4  | pos. 11  | Материал: Сталь 12Х18Н10Т ГОСТ 5632-72 (density 1000 kg/m3); Масса: 0.003438; Раздел спецификации: Стандартные изделия; additional columns: C.8.21; Сталь 12Х18Н10Т ГОСТ 5632-72
  - Component [standard]: Шайба C.10.21 ГОСТ 11371-78  | qty 4  | pos. 11  | Материал: Сталь 12Х18Н10Т ГОСТ 5632-72 (density 1000 kg/m3); Масса: 0.003438; Раздел спецификации: Стандартные изделия; Рассекать на разрезах: no; additional columns: Сталь 12Х18Н10Т ГОСТ 5632-72
  - Component [standard]: Шайба 10 ГОСТ 6402-70  | qty 4  | pos. 10  | Масса: 0.00201; Раздел спецификации: Стандартные изделия; Примечание: Нерж.; additional columns: 8; Без указания материала
  - Component [standard]: Гайка М10-6H.21.12Х18Н10Т ГОСТ 5915-70  | qty 4  | pos. 9  | Масса: 0.01022; Раздел спецификации: Стандартные изделия; additional columns: М8-6H.21.12Х18Н10Т; Сталь 12Х18Н10Т ГОСТ 5632-72
  - Component [standard]: Болт М10x1,25-6gx60 (S16) ГОСТ 7798-70  | qty 4  | pos. 8  | Масса: 0.0467; Раздел спецификации: Стандартные изделия; Рассекать на разрезах: no; additional columns: Сталь 12Х18Н10Т ГОСТ 5632-72
  - Component [detail]: Заглушка @2~25 FV PPR ф. "FV-Plast"  | qty 4  | pos. 12  | Материал: Полипропилен  ГОСТ 26996-86 (density 900 kg/m3); Масса: 0.0161976; Раздел спецификации: Прочие изделия
- Part/product: Магна Ins 10-375-3-1,1-PP-Y-E-N-K-0-0-L-0-B-0-X-M  | designation М10-00.00.000-PP-375-1,1кВт-M-EPDM
    Материал: Полипропилен  ГОСТ 26996-86 (density 900 kg/m3)
    Масса: 15.6383
  - Component [assembly]: Корпус полипропилен 375 1,1кВт  / с разъёмной муфтой  | designation М10-00.20.000-PP-375-1,1кВт-M  | pos. 2  | Материал: Полипропилен  ГОСТ 26996-86 (density 900 kg/m3); Масса: 5.65999; Раздел спецификации: Сборочные единицы; Форматы листов документа: 3xA3; Примечание: @100~)3xA3@101~)3xA3
  - Component [detail]: Электродвигатель / АИР 71B2 IM 3081 IP55 ф."Элком"  | pos. 14  | Масса: 8.3; Раздел спецификации: Прочие изделия; Примечание: См. заказ
  - Component [assembly]: Вал  | designation М10-00.15.000-1,1кВт-375  | pos. 1
      Материал: Полипропилен  ГОСТ 26996-86 (density 900 kg/m3)
      Масса: 0.804509
      Раздел спецификации: Сборочные единицы
      Форматы листов документа: 2xA3
      Примечание: @100~)2xA3
      source file: М10-00.15.000 - Вал.a3d
  - Component [detail]: Крышка  | designation М10-00.00.002  | pos. 4
      Материал: Полипропилен  ГОСТ 26996-86 (density 900 kg/m3)
      Масса: 0.324102
      Раздел спецификации: Детали
      Форматы листов документа: 4xA4
      Примечание: @100~)4xA4
      source file: М10-00.00.002 - Крышка.cdw, М10-00.00.002 - Крышка.m3d
  - Component [detail]: Импеллер Магна10  | designation М10-00.00.001  | pos. 3  | Масса: 0.169927; Раздел спецификации: Детали; Форматы листов документа: A3; source file: М10-00.00.001 - Импеллер Магна10.cdw, М10-00.00.001 - Импеллер Магна10.m3d
  - Component [detail]: Защитная втулка  | designation М10-00.00.003  | pos. 5  | Масса: 0.0193569; Раздел спецификации: Детали; Форматы листов документа: A4; source file: D:\Magna\Магна Ins\Магна ins 10\М10-00.00.000\3Д\М10-00.00.003 - Защитная втулка.cdw, М10-00.00.003 - Защитная втулка.m3d
  - Component [detail]: Втулка ответная  | designation М10А-00.00.003-01  | pos. 6  | Масса: 0.031838; Раздел спецификации: Детали; Форматы листов документа: A4; Примечание: Заим.; source file: D:\AquaProf\АкваProf 190\3Д модель\..\..\..\Magna\Магна Ins\Магна ins 10\М10-00.00.000\3Д\М10А-00.00.003-01 - Втулка ответная.cdw, D:\AquaProf\АкваProf 190\3Д модель\М10А-00.00.003 - Втулка ответная.m3d
  - Component [standard]: Шайба C.10.21 ГОСТ 11371-78  | qty 4  | pos. 11  | Материал: Сталь 12Х18Н10Т ГОСТ 5632-72 (density 1000 kg/m3); Масса: 0.003438; Раздел спецификации: Стандартные изделия; Рассекать на разрезах: no; additional columns: Сталь 12Х18Н10Т ГОСТ 5632-72
  - Component [standard]: Шайба 10 ГОСТ 6402-70  | qty 4  | pos. 10  | Масса: 0.00201; Раздел спецификации: Стандартные изделия; Примечание: Нерж.; additional columns: 8; Без указания материала
  - Component [standard]: Гайка М10-6H.21.12Х18Н10Т ГОСТ 5915-70  | qty 4  | pos. 9  | Масса: 0.01022; Раздел спецификации: Стандартные изделия; additional columns: М8-6H.21.12Х18Н10Т; Сталь 12Х18Н10Т ГОСТ 5632-72
  - Component [standard]: Болт М10x1,25-6gx60 (S16) ГОСТ 7798-70  | qty 4  | pos. 8  | Масса: 0.0467; Раздел спецификации: Стандартные изделия; Рассекать на разрезах: no; additional columns: Сталь 12Х18Н10Т ГОСТ 5632-72
  - Component [detail]: Заглушка @2~25 FV PPR ф. "FV-Plast"  | qty 4  | pos. 12  | Материал: Полипропилен  ГОСТ 26996-86 (density 900 kg/m3); Масса: 0.0161976; Раздел спецификации: Прочие изделия
- Part/product: Магна Ins 10-425-3-1,1-PP-Y-E-N-K-0-0-L-0-B-0-X-R  | designation М10-00.00.000-PP-425-1,1кВт-R-EPDM
    Материал: Полипропилен  ГОСТ 26996-86 (density 900 kg/m3)
    Масса: 15.069
  - Component [assembly]: Корпус полипропилен 425 1,1кВт с резьбовым переходником  | designation М10-00.20.000-PP-425-1,1кВт-R  | pos. 2  | Материал: Полипропилен  ГОСТ 26996-86 (density 900 kg/m3); Масса: 4.98891; Раздел спецификации: Сборочные единицы; Форматы листов документа: 3xA3; Примечание: @100~)3xA3@101~)3xA3
  - Component [detail]: Электродвигатель / АИР 71B2 IM 3081 IP55 ф."Элком"  | pos. 14  | Масса: 8.3; Раздел спецификации: Прочие изделия; Примечание: См. заказ
  - Component [assembly]: Вал  | designation М10-00.15.000-1,1кВт-425  | pos. 1
      Материал: Полипропилен  ГОСТ 26996-86 (density 900 kg/m3)
      Масса: 0.906297
      Раздел спецификации: Сборочные единицы
      Форматы листов документа: 2xA3
      Примечание: @100~)2xA3
      source file: М10-00.15.000 - Вал.a3d
  - Component [detail]: Крышка  | designation М10-00.00.002  | pos. 4
      Материал: Полипропилен  ГОСТ 26996-86 (density 900 kg/m3)
      Масса: 0.324102
      Раздел спецификации: Детали
      Форматы листов документа: 4xA4
      Примечание: @100~)4xA4
      source file: М10-00.00.002 - Крышка.cdw, М10-00.00.002 - Крышка.m3d
  - Component [detail]: Импеллер Магна10  | designation М10-00.00.001  | pos. 3  | Масса: 0.169927; Раздел спецификации: Детали; Форматы листов документа: A3; source file: М10-00.00.001 - Импеллер Магна10.cdw, М10-00.00.001 - Импеллер Магна10.m3d
  - Component [detail]: Защитная втулка  | designation М10-00.00.003  | pos. 5  | Масса: 0.0193569; Раздел спецификации: Детали; Форматы листов документа: A4; source file: D:\Magna\Магна Ins\Магна ins 10\М10-00.00.000\3Д\М10-00.00.003 - Защитная втулка.cdw, М10-00.00.003 - Защитная втулка.m3d
  - Component [detail]: Втулка ответная  | designation М10А-00.00.003-01  | pos. 6  | Масса: 0.031838; Раздел спецификации: Детали; Форматы листов документа: A4; Примечание: Заим.; source file: D:\AquaProf\АкваProf 190\3Д модель\..\..\..\Magna\Магна Ins\Магна ins 10\М10-00.00.000\3Д\М10А-00.00.003-01 - Втулка ответная.cdw, D:\AquaProf\АкваProf 190\3Д модель\М10А-00.00.003 - Втулка ответная.m3d
  - Component [standard]: Шайба C.10.21 ГОСТ 11371-78  | qty 4  | pos. 11  | Материал: Сталь 12Х18Н10Т ГОСТ 5632-72 (density 1000 kg/m3); Масса: 0.003438; Раздел спецификации: Стандартные изделия; additional columns: C.8.21; Сталь 12Х18Н10Т ГОСТ 5632-72
  - Component [standard]: Шайба C.10.21 ГОСТ 11371-78  | qty 4  | pos. 11  | Материал: Сталь 12Х18Н10Т ГОСТ 5632-72 (density 1000 kg/m3); Масса: 0.003438; Раздел спецификации: Стандартные изделия; Рассекать на разрезах: no; additional columns: Сталь 12Х18Н10Т ГОСТ 5632-72
  - Component [standard]: Шайба 10 ГОСТ 6402-70  | qty 4  | pos. 10  | Масса: 0.00201; Раздел спецификации: Стандартные изделия; Примечание: Нерж.; Рассекать на разрезах: no; additional columns: 10; Без указания материала
  - Component [standard]: Гайка М10x1,25-6H(S16) ГОСТ 5915-70  | qty 4  | pos. 9  | Масса: 0.01022; Раздел спецификации: Стандартные изделия; Рассекать на разрезах: no; additional columns: М10x1,25-6H (S16); Сталь 12Х18Н10Т ГОСТ 5632-72
  - Component [standard]: Болт М10-6gx60.21.12Х18Н10Т ГОСТ 7798-70  | qty 4  | pos. 8  | Масса: 0.0467; Раздел спецификации: Стандартные изделия; additional columns: М8-6gx55.21.12Х18Н10Т; Сталь 12Х18Н10Т ГОСТ 5632-72
  - Component [detail]: Заглушка @2~25 FV PPR ф. "FV-Plast"  | qty 4  | pos. 12  | Материал: Полипропилен  ГОСТ 26996-86 (density 900 kg/m3); Масса: 0.0161976; Раздел спецификации: Прочие изделия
